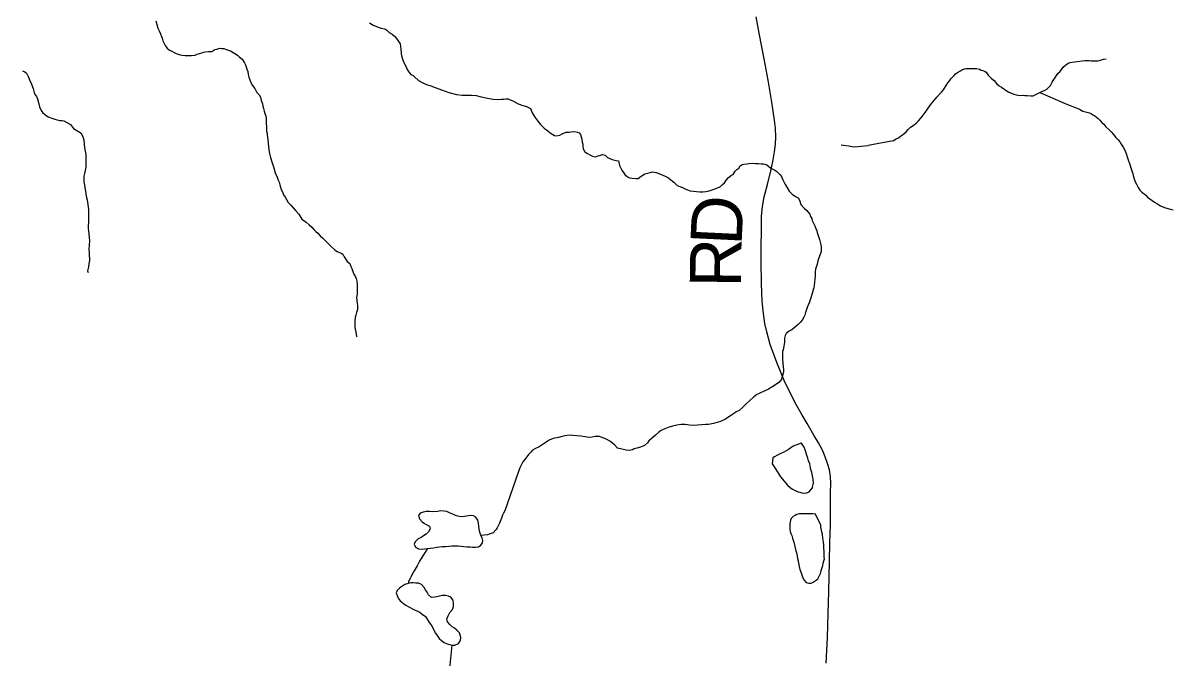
# Model space of a CAD drawing. Extents: x 103424 to 286016, y 38711 to 110967.
# Drawn here: x 127210 to 133964, y 103483 to 107218 of the extents above; entities that cross this region are included whole.
import ezdxf

# ---------------------------------------------------------------- set-up
doc = ezdxf.new("R2010")
doc.units = 0
for name, color, linetype in [('GM_X_Minor_Lake', 7, 'Continuous'), ('GM_X_Minor_River', 7, 'Continuous'), ('GM_X_Township_Road', 7, 'Continuous'), ('GM_X_Township_Road_Text', 7, 'Continuous')]:
    doc.layers.add(name, color=color, linetype=linetype)

msp = doc.modelspace()

# ---------------------------------------------------------------- linework, layer by layer
at = {"layer": 'GM_X_Minor_Lake'}
for points in [[(131792.9, 104742.9), (131744.6, 104726.2), (131730.6, 104716), (131718.6, 104705.8), (131704.5, 104697.6), (131690.5, 104689.3), (131672.4, 104683.1), (131660.3, 104676.9), (131648.3, 104670.7), (131636.2, 104662.5), (131626.2, 104656.4), (131622.6, 104622), (131628.8, 104609.9), (131641.1, 104591.9), (131651.4, 104575.8), (131661.7, 104559.8), (131671.2, 104544.9)], [(131671.2, 104544.9), (131712.9, 104495.7), (131727.2, 104481.6), (131741.5, 104471.7), (131761.8, 104461.8), (131774, 104455.9), (131784.1, 104453.9), (131796.3, 104450), (131808.4, 104448.1), (131826.5, 104450.3), (131838.6, 104456.5), (131846.6, 104466.7), (131858.5, 104480.9), (131860.4, 104491.1), (131864.3, 104507.3), (131864, 104531.5), (131855.5, 104569.8), (131849.2, 104587.9), (131847, 104598), (131844.9, 104610.1), (131842.7, 104622.2), (131836.5, 104638.3), (131832.3, 104654.4), (131828.1, 104666.5), (131823.9, 104676.5), (131821.8, 104686.6), (131815.5, 104704.7), (131809.3, 104718.8), (131801, 104732.9), (131794.9, 104742.9), (131792.9, 104742.9)], [(129652.1, 104341.2), (129622, 104339), (129603.8, 104340.9), (129585.7, 104340.8), (129567.6, 104336.6), (129549.6, 104330.5), (129539.6, 104316.3), (129545.8, 104298.2), (129560, 104280.1), (129574.1, 104270.1), (129588.3, 104262.2), (129604.4, 104254.2), (129608.6, 104238.1), (129598.6, 104219.9), (129584.6, 104207.7), (129568.6, 104197.5), (129554.6, 104187.3), (129536.5, 104179.2), (129520.5, 104162.9), (129514.6, 104148.8), (129522.7, 104130.7), (129538.9, 104120.7), (129557, 104118.8), (129593.3, 104123.1), (129609.3, 104125.2), (129627.4, 104127.4), (129645.5, 104131.5), (129663.7, 104131.6), (129679.7, 104133.8), (129699.9, 104133.9), (129736.1, 104138.2), (129772.3, 104138.4), (129790.4, 104136.5), (129806.6, 104134.6), (129824.7, 104132.7), (129842.8, 104132.9), (129856.9, 104131), (129875, 104131.1), (129893.1, 104133.2)], [(129893.1, 104133.2), (129907.2, 104141.4), (129917.1, 104155.6), (129919, 104169.7), (129914.9, 104185.8), (129906.8, 104199.8), (129900.6, 104217.9), (129896.4, 104236.1), (129892.2, 104272.3), (129888, 104290.4), (129877.8, 104306.5), (129863.7, 104314.5), (129845.6, 104316.4), (129809.4, 104312.1), (129789.2, 104309.9), (129771.1, 104313.8), (129757, 104317.8), (129740.8, 104325.7), (129726.7, 104331.7), (129706.5, 104339.6), (129688.4, 104343.5), (129670.3, 104345.4), (129652.1, 104341.2)], [(131876.5, 104325.6), (131860.3, 104327.5), (131821.9, 104327.1), (131811.8, 104327), (131791.6, 104326.8), (131781.5, 104326.7), (131767.4, 104322.5), (131757.4, 104316.3), (131747.4, 104312.2), (131733.4, 104299.9), (131729.4, 104289.8), (131727.5, 104279.7), (131725.7, 104267.5), (131725.8, 104257.4), (131725.9, 104245.3), (131726, 104235.2), (131728.2, 104223.1), (131732.4, 104211), (131736.6, 104199), (131740.8, 104182.8), (131747, 104166.7), (131749.5, 104159.5)], [(131749.5, 104159.5), (131761.8, 104108.3), (131766.1, 104092.2), (131768.2, 104078.1), (131770.4, 104064), (131774.6, 104049.9), (131776.8, 104035.7), (131781.1, 104017.6), (131785.3, 103999.5), (131791.6, 103979.3), (131797.9, 103961.2), (131802, 103951.2), (131808.2, 103939.1), (131822.6, 103923.1), (131836.7, 103919.2), (131850.9, 103919.3), (131863, 103923.5), (131881, 103935.8), (131891, 103944), (131900.9, 103964.3), (131906.8, 103976.4), (131910.7, 103990.6), (131914.5, 104004.8), (131920.4, 104023), (131922.2, 104037.2), (131926.1, 104049.3), (131930, 104061.5), (131927.9, 104073.6), (131927.7, 104089.8), (131927.5, 104107.9), (131925.3, 104124.1), (131925.1, 104142.3), (131924.8, 104160.4), (131920.5, 104182.6), (131918.2, 104206.8), (131914.1, 104218.9), (131911.9, 104231), (131907.7, 104249.1), (131907.5, 104259.2), (131876.5, 104325.6)], [(129663, 103841.4), (129655.6, 103839.2), (129635.5, 103835.1), (129615.4, 103834.9), (129599.2, 103848.9), (129591, 103865), (129580.8, 103879.1), (129572.7, 103893.1), (129556.5, 103911.2), (129540.3, 103919.1), (129524.2, 103919), (129508.1, 103920.9), (129494, 103920.8), (129477.9, 103916.7), (129459.8, 103910.5), (129441.8, 103898.3), (129427.8, 103888.1), (129413.8, 103875.9), (129407.8, 103861.7), (129420.1, 103829.6), (129432.3, 103813.5), (129450.5, 103799.5), (129464.7, 103789.5), (129478.8, 103781.6), (129515.2, 103761.7), (129533.4, 103753.7), (129547.5, 103747.8), (129561.7, 103735.8), (129579.9, 103721.8), (129590.1, 103705.7), (129602.3, 103687.7), (129614.4, 103673.6)], [(129614.4, 103673.6), (129624.6, 103655.6), (129630.8, 103637.5), (129638.9, 103623.4), (129649.1, 103609.4), (129661.3, 103593.3), (129675.5, 103581.3), (129689.6, 103569.3), (129707.8, 103561.4), (129736, 103553.5), (129754.2, 103553.6), (129774.2, 103563.8), (129786.2, 103580), (129788.1, 103598.2), (129779.8, 103626.4), (129765.6, 103642.4), (129751.5, 103654.4), (129737.3, 103660.4), (129723.1, 103674.4), (129711, 103690.4), (129706.8, 103708.5), (129714.7, 103726.7), (129724.7, 103745), (129738.6, 103763.2), (129744.6, 103781.4), (129746.4, 103799.5), (129744.3, 103817.7), (129730.1, 103835.7), (129716, 103841.7), (129697.8, 103845.6), (129679.7, 103845.5), (129663, 103841.4)]]:
    msp.add_lwpolyline(points, dxfattribs=at)
at = {"layer": 'GM_X_Minor_River'}
for points in [[(127993, 107229.9), (128005.6, 107187.6), (128011.8, 107171.5), (128020.1, 107153.4), (128026.4, 107137.3), (128030.5, 107127.2), (128034.7, 107113.1), (128041, 107097), (128047.2, 107085), (128059.5, 107068.9), (128073.8, 107057), (128088, 107051), (128100.2, 107043.1), (128112.4, 107037.1), (128136.7, 107029.3), (128148.8, 107027.4), (128165, 107025.6), (128185.2, 107025.7), (128203.4, 107025.9), (128223.6, 107028.2), (128235.6, 107034.3), (128249.7, 107038.5), (128263.8, 107042.7), (128273.9, 107044.8), (128286, 107047), (128302.1, 107049.1), (128312.2, 107049.2), (128322.3, 107049.3), (128340.3, 107061.6), (128352.4, 107063.8), (128370.5, 107070), (128380.7, 107068.1), (128392.8, 107068.2), (128402.9, 107064.3), (128419.1, 107058.4), (128433.3, 107054.5), (128474, 107028.6), (128484.2, 107018.6), (128500.6, 107004.7), (128506.7, 106994.6), (128515, 106982.6), (128521.2, 106970.5), (128525.3, 106958.4), (128529.5, 106946.4), (128533.7, 106932.3), (128535.9, 106914.1), (128540.2, 106898), (128546.4, 106881.9), (128552.6, 106867.8), (128563, 106849.7), (128575.3, 106831.7), (128587.7, 106807.6), (128602, 106793.6), (128608.2, 106781.5), (128610.3, 106771.4), (128612.5, 106761.4), (128616.6, 106751.3), (128620.8, 106741.2), (128622.9, 106727.1), (128627.2, 106713), (128631.4, 106698.9), (128635.6, 106684.8), (128639.8, 106670.7), (128642, 106652.6), (128642.3, 106630.4), (128644.6, 106604.1), (128644.9, 106579.9), (128649.1, 106565.8), (128649.2, 106555.7), (128651.3, 106545.6), (128651.5, 106531.5), (128653.8, 106509.3), (128656, 106489.1), (128658.2, 106471), (128662.5, 106448.8), (128668.9, 106424.6), (128677.3, 106394.4), (128687.8, 106364.2), (128696.2, 106336), (128706.6, 106309.8), (128712.8, 106291.7), (128719, 106279.7), (128723.3, 106263.6), (128731.6, 106237.4)], [(129251.5, 107218.2), (129271.8, 107204.2), (129288.1, 107198.3), (129302.3, 107192.4), (129320.5, 107186.5), (129340.8, 107182.7), (129353, 107174.7), (129367.3, 107160.8), (129383.5, 107150.8), (129399.8, 107138.9), (129410.1, 107126.8), (129430.6, 107094.7), (129435.1, 107062.5), (129437.4, 107038.2), (129439.6, 107024.1), (129445.8, 107006), (129450, 106993.9), (129456.2, 106977.8), (129464.5, 106963.8), (129472.8, 106943.7), (129485.1, 106925.6), (129495.4, 106911.6), (129505.5, 106909.6), (129515.7, 106899.7), (129540.2, 106879.7), (129564.6, 106865.8), (129586.9, 106855.9), (129611.3, 106848.1), (129637.6, 106838.2), (129674.1, 106824.5), (129718.8, 106808.8), (129763.3, 106797.1), (129795.7, 106793.4), (129820, 106791.6), (129838.1, 106791.8), (129852.3, 106791.9), (129878.6, 106790.2), (129908.9, 106782.4), (129945.4, 106774.7), (129979.8, 106768.9), (130010.1, 106767.2), (130028.3, 106769.4), (130042.4, 106769.6), (130054.5, 106771.7), (130066.6, 106771.8), (130078.8, 106765.9), (130095, 106760), (130125.5, 106742.1), (130153.9, 106732.3), (130176.2, 106726.5), (130198.5, 106714.6), (130209, 106688.4), (130223.4, 106662.3), (130241.8, 106640.3), (130258.2, 106620.2), (130278.7, 106598.2), (130301.1, 106582.3), (130315.4, 106570.3), (130329.6, 106560.3), (130339.8, 106554.4), (130349.9, 106552.5), (130372.1, 106556.7), (130386.1, 106565), (130408.2, 106575.3), (130424.4, 106575.4), (130436.5, 106575.6), (130458.7, 106577.8), (130474.9, 106573.9), (130485, 106570), (130493.2, 106560), (130497.4, 106547.9), (130501.6, 106533.8), (130503.8, 106515.6), (130506, 106503.5), (130506.1, 106491.4), (130508.3, 106477.3)], [(132331.9, 106521), (132336.7, 106525.3), (132352.6, 106535.7), (132364.6, 106542), (132376.6, 106550.3), (132388.5, 106558.6), (132398.5, 106566.8), (132410.4, 106577.2), (132422.3, 106589.5), (132436.2, 106603.9), (132458.1, 106618.4), (132472, 106628.8), (132483.9, 106641.1), (132497.8, 106657.5), (132511.6, 106673.9), (132523.4, 106690.3), (132537.1, 106710.7), (132552.9, 106735.3), (132572.6, 106759.9), (132590.4, 106780.4), (132606.2, 106798.8), (132618.1, 106809.2), (132630, 106823.5), (132635.8, 106833.7), (132655.5, 106864.4), (132667.3, 106878.7), (132673.2, 106888.9), (132693, 106907.5), (132700.9, 106917.7), (132712.9, 106926), (132730.9, 106936.4), (132742.9, 106942.7), (132762.9, 106949.1), (132775, 106949.3), (132793.2, 106949.7), (132811.3, 106950), (132825.5, 106950.2), (132841.7, 106946.5), (132851.9, 106940.6), (132862, 106936.8), (132872.2, 106932.9), (132882.4, 106927), (132892.8, 106911.1), (132913.3, 106891.2), (132929.6, 106879.4), (132942.1, 106861.4), (132958.5, 106847.6), (132972.7, 106839.8), (133005.4, 106816.1), (133015.6, 106810.2), (133029.9, 106804.4), (133044.1, 106798.6), (133058.3, 106794.9), (133070.4, 106793), (133080.6, 106791.2), (133098.7, 106791.5), (133108.8, 106789.7), (133122.9, 106790), (133145.2, 106788.3), (133159.3, 106788.6), (133177.3, 106799), (133197.3, 106807.5), (133213.3, 106815.8), (133225.3, 106820.1), (133239.3, 106828.4), (133251.2, 106838.7), (133261.1, 106849), (133270.9, 106869.4), (133276.7, 106879.6), (133290.5, 106898), (133296.4, 106908.2), (133306.2, 106922.5), (133316.2, 106930.8), (133326, 106943.1), (133335.9, 106957.4), (133349.7, 106971.8), (133363.7, 106980.1), (133375.7, 106984.4), (133401.9, 106988.9), (133462.3, 106996), (133472.4, 106996.2), (133488.5, 106996.5), (133500.7, 106994.7), (133516.8, 106995), (133537, 106995.4), (133549.1, 106997.6), (133561.1, 106999.8), (133573.1, 107004.1), (133587.2, 107006.4)], [(127208.7, 106935.2), (127220.9, 106929.3), (127231.1, 106921.3), (127243.4, 106899.2), (127251.7, 106879.1), (127260.1, 106856.9), (127270.5, 106830.8), (127278.9, 106800.6), (127291.2, 106784.5), (127295.4, 106770.4), (127301.7, 106748.3), (127308.1, 106724.1), (127318.4, 106702), (127326.7, 106687.9), (127345, 106674), (127359.3, 106664), (127379.6, 106656.1), (127397.8, 106650.3), (127412, 106646.4), (127428.2, 106642.5), (127440.3, 106642.6), (127450.4, 106640.7), (127491.1, 106618.9), (127507.5, 106596.8), (127538, 106579), (127552.3, 106569), (127562.6, 106546.9), (127568.9, 106528.8), (127571.2, 106504.6), (127573.5, 106482.4), (127577.7, 106462.2), (127580, 106444), (127580.2, 106425.9), (127580.4, 106409.7), (127580.6, 106391.5), (127580.7, 106379.4), (127580.8, 106369.3), (127577, 106349.1), (127573.2, 106330.9), (127569.4, 106314.7), (127569.6, 106294.5), (127569.7, 106280.3), (127572, 106264.2), (127574.2, 106246), (127578.4, 106227.9), (127582.8, 106197.6), (127589.1, 106175.5), (127593.5, 106149.3), (127595.9, 106119), (127596.3, 106084.7), (127596.6, 106058.4), (127596.8, 106040.2), (127594.9, 106026.1), (127595, 106016), (127595.2, 106005.9), (127597.3, 105993.8), (127597.5, 105975.6), (127599.8, 105953.4), (127602, 105937.3), (127600.3, 105909), (127598.6, 105884.7), (127600.8, 105864.5), (127601.1, 105844.3), (127603.2, 105834.3), (127601.4, 105818.1), (127597.6, 105799.9), (127595.7, 105781.7)], [(133197.3, 106807.5), (133333.6, 106749.3), (133360, 106737.7), (133386.4, 106728), (133410.8, 106718.4), (133431.1, 106710.7), (133451.5, 106698.9), (133473.8, 106693.3), (133490, 106687.5), (133500.2, 106683.6), (133510.4, 106675.7), (133520.6, 106669.9), (133530.9, 106662), (133541.1, 106654.1), (133551.3, 106646.2), (133561.6, 106634.2), (133573.9, 106622.3), (133586.3, 106606.4), (133604.8, 106590.6), (133617.1, 106576.6), (133631.6, 106560.7), (133646, 106542.8), (133658.4, 106528.9), (133668.7, 106517), (133677, 106503), (133687.4, 106487), (133697.8, 106469), (133706.2, 106449), (133712.6, 106428.9), (133719.1, 106404.8), (133725.4, 106390.7), (133729.7, 106378.7), (133734, 106364.6), (133738.2, 106352.6), (133740.4, 106340.5), (133744.7, 106328.5), (133746.9, 106318.4), (133751.1, 106306.4), (133755.4, 106294.3), (133759.6, 106282.3), (133765.9, 106268.2), (133776.4, 106248.2), (133786.8, 106232.3), (133799.1, 106220.4), (133811.4, 106210.5), (133821.6, 106202.6), (133831.9, 106192.7), (133872.8, 106163.1), (133887, 106155.3), (133897.3, 106147.4), (133907.5, 106141.5), (133921.7, 106135.7), (133937.9, 106129.9), (133958.3, 106122.2), (133982.6, 106116.6)], [(132334.8, 106523.6), (132186, 106495.2)], [(130508.3, 106477.3), (130518.6, 106459.2), (130534.9, 106449.3), (130549.1, 106441.3), (130559.3, 106435.4), (130569.4, 106431.4), (130579.6, 106429.5), (130621.8, 106442.1), (130638.1, 106438.2), (130652.3, 106426.2), (130678.7, 106414.4), (130703, 106408.5), (130717.2, 106406.7), (130723.6, 106378.4), (130736, 106350.3), (130754.5, 106326.2), (130770.8, 106312.3), (130781, 106306.3), (130797.1, 106304.4), (130819.4, 106302.6), (130833.5, 106300.8), (130849.5, 106315.1), (130871.6, 106329.4), (130889.7, 106333.7), (130903.8, 106337.8), (130915.9, 106340), (130938.2, 106336.1), (130964.5, 106326.3), (130990.9, 106314.5), (131011.2, 106306.6), (131025.5, 106294.6), (131041.8, 106280.6), (131062.2, 106260.6), (131094.7, 106248.8), (131117.1, 106236.9), (131139.4, 106229.1), (131196, 106223.6), (131214.2, 106223.8), (131230.3, 106226), (131250.5, 106228.2), (131274.6, 106236.5), (131296.7, 106244.8), (131316.8, 106255.1), (131328.8, 106267.3), (131340.8, 106275.5), (131352.7, 106293.8), (131364.7, 106308.1), (131382.7, 106320.4), (131392.8, 106324.5), (131404.6, 106344.8), (131414.6, 106355), (131424.6, 106363.2), (131432.6, 106375.4), (131444.6, 106383.6), (131454.7, 106385.7), (131472.8, 106387.9), (131484.9, 106390.1), (131505.1, 106392.3), (131523.3, 106390.5), (131541.5, 106390.6), (131557.6, 106388.8), (131567.7, 106388.9), (131577.9, 106387), (131590, 106383), (131602.3, 106373.1), (131618.6, 106361.1), (131636.8, 106351.2), (131649.1, 106343.2), (131667.4, 106325.2), (131675.7, 106313.2), (131684, 106293.1), (131692.2, 106279), (131700.5, 106265), (131721.1, 106226.8), (131739.5, 106208.8), (131759.8, 106194.9), (131774.1, 106186.9), (131782.3, 106174.9), (131790.7, 106148.7), (131809.1, 106126.7), (131825.4, 106112.7), (131833.6, 106102.7), (131843.9, 106090.7), (131848, 106078.6), (131854.3, 106066.5), (131856.4, 106054.4), (131864.7, 106038.4), (131872.9, 106022.3), (131879.2, 106008.2), (131885.4, 105994.1), (131887.5, 105984.1), (131889.7, 105971.9), (131896, 105953.8), (131900.1, 105941.8), (131904.3, 105927.7), (131908.6, 105911.5), (131910.8, 105897.4), (131911.1, 105871.2), (131905.2, 105855), (131901.3, 105844.8), (131897.3, 105834.7)], [(132027, 106500.6), (132042.4, 106497.2), (132070.6, 106493.3), (132104.9, 106487.5), (132186, 106495.2)], [(128731.6, 106237.4), (128737.9, 106223.3), (128744.1, 106205.2), (128754.4, 106191.1), (128762.6, 106177.1), (128772.9, 106161), (128787.3, 106145), (128801.6, 106129), (128815.9, 106113), (128834.3, 106091), (128852.8, 106062.9), (128877.3, 106044.9), (128895.6, 106028.9), (128912, 106015), (128922.2, 106000.9), (128934.5, 105988.9), (128946.7, 105979), (128961, 105965), (128975.3, 105951), (128991.7, 105935), (129008, 105919), (129024.4, 105900.9), (129046.8, 105881), (129061.1, 105871), (129073.3, 105865.1), (129083.4, 105861.1), (129093.6, 105855.2), (129101.8, 105841.1), (129114.2, 105823.1), (129120.3, 105813), (129134.6, 105801.1), (129140.9, 105782.9), (129147.1, 105770.9), (129153.3, 105754.8), (129159.6, 105738.7), (129167.8, 105722.6), (129172, 105712.6), (129176.2, 105696.4), (129178.4, 105682.3), (129178.6, 105666.2), (129178.8, 105652), (129178.9, 105635.9), (129179.1, 105619.7), (129175.3, 105601.5), (129177.8, 105565.2), (129179.9, 105553.1), (129180.2, 105530.9), (129174.3, 105512.6), (129170.5, 105496.4), (129166.6, 105482.2), (129164.8, 105466.1), (129164.9, 105453.9), (129165, 105441.8), (129165.2, 105429.7), (129167.4, 105413.6), (129169.6, 105397.4), (129171.8, 105383.3), (129173.9, 105373.2), (129176, 105369.2)], [(131897.3, 105834.7), (131891.5, 105816.4), (131885.7, 105796.2), (131879.8, 105780), (131875.9, 105767.8), (131874.1, 105751.6), (131874.3, 105729.4), (131872.5, 105711.2), (131870.7, 105691), (131868.9, 105672.8), (131867.1, 105658.6), (131863.1, 105648.5), (131861.2, 105638.4), (131857.4, 105624.2), (131847.6, 105593.8), (131839.8, 105569.5), (131831.9, 105551.2), (131826.1, 105537), (131818.3, 105512.7), (131814.4, 105496.5), (131808.5, 105484.3), (131798.6, 105468.1), (131788.6, 105455.9), (131774.6, 105441.6), (131760.7, 105429.3), (131748.6, 105421.1), (131736.6, 105410.9), (131722.6, 105402.7), (131704.6, 105388.4), (131698.7, 105376.2), (131694.8, 105362), (131695.1, 105335.8), (131693.2, 105325.6), (131691.3, 105313.5), (131685.5, 105293.2), (131681.6, 105283.1), (131681.7, 105273), (131681.8, 105258.9), (131682.1, 105236.7), (131684.4, 105214.5), (131686.7, 105192.3), (131688.9, 105176.1), (131689, 105166), (131687.1, 105155.9), (131683.2, 105141.7), (131675.4, 105115.4), (131661.5, 105101.1), (131647.4, 105090.9), (131625.4, 105076.5), (131599.3, 105060.1), (131571.2, 105047.7), (131553.1, 105039.4), (131541.1, 105033.2), (131531, 105029.1), (131511, 105014.8), (131469, 104974), (131449, 104955.6), (131427.1, 104935.2), (131409, 104926.9), (131399, 104918.7), (131382.9, 104908.5), (131366.9, 104898.2), (131346.9, 104883.9), (131316.7, 104871.4), (131276.4, 104858.9), (131256.3, 104854.7), (131246.2, 104852.6), (131230.1, 104852.4), (131205.9, 104850.1), (131181.6, 104849.9), (131157.4, 104847.6), (131135.2, 104849.4), (131123, 104851.3), (131108.9, 104853.2), (131086.7, 104853), (131060.5, 104848.7), (131034.3, 104842.4), (131010.1, 104836.1), (130990, 104827.8), (130975.9, 104821.6), (130963.9, 104815.4), (130953.9, 104807.2), (130933.9, 104790.9), (130919.9, 104776.6), (130905.9, 104764.3), (130895.9, 104756.2), (130888, 104744), (130870, 104729.6), (130845.8, 104719.3), (130825.7, 104713), (130809.6, 104708.8), (130799.5, 104704.7), (130779.4, 104700.5), (130761.2, 104702.3), (130710.6, 104713.9), (130696.2, 104732), (130681.9, 104743.9), (130665.7, 104753.9), (130651.4, 104761.8), (130637.2, 104769.7), (130625.1, 104773.7)], [(127595.7, 105781.7), (127590, 105757.4), (127594.1, 105747.3)], [(130625.1, 104773.7), (130604.8, 104781.5), (130594.7, 104781.4), (130580.5, 104781.3), (130562.4, 104779.1), (130540.2, 104776.8), (130519.9, 104780.7), (130495.6, 104784.5), (130471.4, 104786.3), (130447.1, 104788), (130428.9, 104789.9), (130412.8, 104787.7), (130400.7, 104785.6), (130384.6, 104781.4), (130364.5, 104777.1), (130332.2, 104770.7), (130308.1, 104760.4), (130280, 104741.9), (130250, 104721.4), (130223.9, 104709.1), (130209.8, 104700.8), (130199.8, 104690.6), (130187.9, 104676.4), (130177.9, 104662.1), (130164, 104645.8), (130154, 104633.6), (130146.1, 104617.4), (130136.3, 104597.1), (130128.4, 104576.8), (130047, 104343.8)], [(130047, 104343.8), (130040.4, 104331.5), (130034.5, 104319.3), (130028.6, 104301.1), (130024.7, 104291), (130016.8, 104272.7), (130008.9, 104256.5), (130003, 104244.3), (129997.1, 104234.1), (129979.1, 104215.8), (129961, 104209.5), (129944.9, 104203.3), (129906.8, 104199.8)], [(129593.3, 104123.1), (129556, 104063.5), (129546.1, 104047.2), (129538.2, 104033), (129532.2, 104020.8), (129526.3, 104010.6), (129520.4, 104000.5), (129514.4, 103990.3), (129506.5, 103978.1), (129500.5, 103968), (129496.6, 103957.8), (129490.7, 103945.7), (129482.8, 103931.4), (129480.8, 103925.4), (129480.9, 103917.3)], [(129736, 103553.5), (129718.2, 103376.9)]]:
    msp.add_lwpolyline(points, dxfattribs=at)
at = {"layer": 'GM_X_Township_Road'}
msp.add_lwpolyline([(131939.3, 103447.7), (131946.5, 103598.3), (131951.3, 103739.2), (131955.7, 103869.5), (131957.6, 103957.7), (131959.5, 104045.8), (131961.8, 104154.5), (131964.2, 104263.3), (131964.9, 104358.6), (131965.5, 104453.9), (131966.2, 104506.3), (131964.2, 104547.6), (131958.3, 104586.9), (131947.8, 104622.9), (131934.1, 104662.9), (131918.4, 104701.5), (131895.4, 104744.8), (131867.9, 104790.6), (131827.3, 104858.1), (131795.6, 104911.6), (131765.1, 104967.5), (131737.6, 105020.5), (131692.4, 105112.3), (131649.1, 105218.4), (131610.5, 105324.5), (131589.5, 105399.2), (131578.4, 105448.3), (131569.8, 105507.3), (131562, 105578.7), (131558.1, 105682.2), (131556.1, 105813.9), (131559.3, 106080.5), (131565.3, 106136.2), (131574.4, 106193.9), (131593.4, 106267.2), (131615.1, 106355.6), (131627.1, 106412.4), (131635.5, 106458.7), (131641.1, 106503.6), (131643.2, 106544.3), (131641.1, 106598.3), (131636.2, 106646), (131619.8, 106751.2), (131599, 106881.6), (131575.5, 107007.1), (131545.7, 107157.2), (131526.8, 107253.3)], dxfattribs=at)

# ---------------------------------------------------------------- texts
at = {"layer": 'GM_X_Township_Road_Text'}
for s, rotation, p in [('D', 87.26328, (131441, 105903.4)), ('R', 89.34817, (131438.3, 105658.4))]:
    msp.add_text(s, height=301.9, rotation=rotation, dxfattribs=at).set_placement(p)

doc.saveas('drawing.dxf')
